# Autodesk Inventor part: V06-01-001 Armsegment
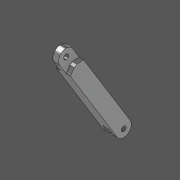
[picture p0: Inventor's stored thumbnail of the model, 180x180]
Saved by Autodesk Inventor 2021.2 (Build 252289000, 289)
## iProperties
RuleStatus: InUse
Company: R-Kon - Rodermund Konstruktion und Entwicklung GmbH
Created: 2020-09
Part Number: V06-01-001 Armsegment
Material: Stahl
Document SubType Name: Modeling
Designer: Felix Rodermund
Engineer: Felix Rodermund
Density: 7.85 g/cm^3
Appearance: Stahl
Mass: 23483.7 g
Surface Area: 1959.26 cm^2
Volume: 2991.55 cm^3
StatusCheck: 1
Title: Teil
Author: Felix Rodermund
Revision Number: 0
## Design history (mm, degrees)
derived "V04-01-000 Gelenkarm Skelett.ipt"
  sketch "yz Armgeometrie"
    geometry: L1 (0, 70.229)-(455.878, 350.229) reference; L2 (455.878, 350.229)-(0, 630.229) reference; L3 (0, -240.046)-(0, 1440.275) reference; L4 (0, 1200.229)-(0, 700.229) reference; L5 (-100, 0.229)-(100, 0.229) reference; L6 (0, 70.229)-(72.973, 600.229) reference; L7 (72.973, 600.229)-(0, 1130.229) reference; L8 (434.944, 384.314)-(-20.935, 104.314) reference; L9 (476.813, 316.145)-(20.935, 36.145) reference; L10 (40, 700.229)-(-40, 700.229) reference; L11 (0, 630.229)-(0, 700.229) reference; L12 (40, 680.229)-(-40, 680.229) reference; L13 (0, 1130.229)-(0, 1200.229) reference; L14 (40, 1200.229)-(-40, 1200.229) reference; A1 r 40 centre (455.878, 350.229) between (476.813, 316.145) and (434.944, 384.314) reference; A2 r 40 centre (0, 70.229) between (20.935, 36.145) and (-20.935, 104.314) reference; 3 further points
    constraints: 1 vertical alignment
  sketch "xz Befestigungslager"
    geometry: L1 (-100, 0)-(100, 0) reference; L2 (100, 0)-(100, 20) reference; L3 (100, 20)-(-100, 20) reference; L4 (-100, 20)-(-100, 0) reference; L5 (140, 0)-(-140, 0) reference; L6 (-15, 20)-(-15, 110.229) reference; L7 (-15, 110.229)-(15, 110.229) reference; L8 (15, 110.229)-(15, 20) reference; L9 (0, 110.229)-(0, 30.229) reference; L10 (-37, 310.229)-(-37, 30.229) reference; L11 (-37, 30.229)-(-17, 30.229) reference; L12 (-17, 30.229)-(-17, 113.229) reference; L13 (-17, 113.229)-(17, 113.229) reference; L14 (17, 113.229)-(17, 30.229) reference; L15 (17, 30.229)-(37, 30.229) reference; L16 (37, 30.229)-(37, 310.229) reference; L17 (0, 390.229)-(0, 310.229) reference; 6 further points
    constraints: 1 other
  sketch "wx Armgelenk"
    geometry: L1 (20.935, 15)-(20.935, -15) reference; L2 (20.935, -15)-(-26.288, -15) reference; L3 (-26.288, 15)-(20.935, 15) reference; L4 (-20.935, -17)-(-20.935, -37) reference; L5 (22.505, -17)-(-20.935, -17) reference; L6 (-20.935, -37)-(125.607, -37) reference; L7 (485, 37)-(485, 15) reference; L8 (485, 15)-(575, 15) reference; L9 (575, 15)-(575, -15) reference; L10 (575, -15)-(485, -15) reference; L11 (485, -15)-(485, -37) reference; L12 (-353.223, 0)-(1265.573, 0) reference; L13 (575, 0)-(495, 0) reference; 2 further points
  sketch "xz Gelenkdetails"
    geometry: L1 (-37, 310.229)-(-37, 30.229) reference; L2 (-37, 30.229)-(-17, 30.229) reference; L3 (-17, 30.229)-(-17, 113.229) reference; L4 (-15, 20)-(-15, 110.229) reference; L5 (-15, 110.229)-(15, 110.229) reference; L6 (15, 110.229)-(15, 20) reference; L7 (37, 30.229)-(37, 310.229) reference; L8 (47, 82.729)-(-47, 82.729) reference; L9 (-47, 82.729)-(-47, 57.729) reference; L10 (-47, 57.729)-(47, 57.729) reference; L11 (47, 57.729)-(47, 82.729) reference; L12 (-15, 57.229)-(15, 57.229) reference; L13 (47, 70.229)-(-47, 70.229) reference; 2 further points
  sketch "yz Kollision"
    geometry: L1 (434.944, 384.314)-(-20.935, 104.314) reference; L2 (476.813, 316.145)-(20.935, 36.145) reference; L3 (20.935, 664.314)-(476.813, 384.314) reference; L4 (-20.935, 596.145)-(434.944, 316.145) reference; L5 (434.944, 316.145)-(476.813, 384.314) reference; L6 (392.338, 358.145)-(434.207, 289.977) reference; L7 (378.42, 349.597)-(416.709, 326.171) reference; L8 (-300.984, -114.635)-(1078.406, 732.585) reference; A1 r 40 centre (455.878, 350.229) between (434.944, 384.314) and (476.813, 316.145) reference; 6 further points; 1 other entity
    constraints: 1 other
  sketch "yz Armsegment Details"
    geometry: C1 r 40 at (455.878, 350.229) reference; C2 r 13 at (455.878, 350.229) reference; 4 further points
    constraints: 1 vertical alignment
sketch "yz basis"
  geometry: L1 (476.813, 316.145)-(20.935, 36.145) reference; L2 (434.944, 384.314)-(-20.935, 104.314) reference; L3 (0, 70.229)-(455.878, 350.229) reference; L4 (378.42, 349.597)-(416.709, 326.171) reference; C1 r 13 at (455.878, 350.229) reference; A1 r 40 centre (455.878, 350.229) between (476.813, 316.145) and (434.944, 384.314) reference; A2 r 40 centre (0, 70.229) between (20.935, 36.145) and (-20.935, 104.314) reference; 1 further point
sketch "xz basis"
  geometry: L1 (37, 30.229)-(37, 310.229) reference; L2 (17, 30.229)-(37, 30.229) reference; L3 (-37, 30.229)-(-17, 30.229) reference; L4 (-37, 310.229)-(-37, 30.229) reference; L5 (-17, 30.229)-(-17, 113.229) reference; L6 (-17, 113.229)-(17, 113.229) reference; L7 (17, 113.229)-(17, 30.229) reference; L8 (-47, 57.729)-(47, 57.729) reference; L9 (47, 57.729)-(47, 82.729) reference; L10 (47, 82.729)-(-47, 82.729) reference; L11 (47, 70.229)-(-47, 70.229) reference; L12 (-47, 82.729)-(-47, 57.729) reference; 1 further point
node "ewx mitte armsegment"
sketch "wx mitte armsegment"
  geometry: L1 (485, -15)-(485, -37) reference; L2 (575, -15)-(485, -15) reference; L3 (485, 37)-(485, 15) reference; L4 (485, 15)-(575, 15) reference; L5 (575, 15)-(575, -15) reference; 1 further point
workplane "Arbeitsebene2"
extrude "Extrusion1" new body sketch "yz basis" stored distance "d3" = 10; taper "d4" = 0 deg
workplane "Arbeitsebene3"
sketch "Skizze8"
  geometry: L1 (-476.813, 285.916)-(-20.935, 5.916) reference; L2 (-434.944, 354.084)-(20.935, 74.084) reference; L3 (-15.706, 96.589)-(-57.575, 28.42); L4 (-57.575, 28.42)-(15.706, -16.589); L5 (15.706, -16.589)-(57.575, 51.58); L6 (57.575, 51.58)-(-15.706, 96.589); A1 r 40 centre (0, 40) between (-20.935, 5.916) and (20.935, 74.084) reference; 5 further points
  constraints: 8 end point, 3 perpendicular, 2 point on line, 1 coincident, 1 collinear, 1 vertical alignment, 4 other
extrude "Extrusion2" cut sketch "Skizze8" stored distance "d5" = 10; taper "d6" = 0 deg
sketch "Skizze9"
  geometry: L1 (485, -15)-(485, -37) reference; L2 (485, 37)-(485, 15) reference; L3 (485, 15)-(575, 15) reference; L4 (575, -15)-(485, -15) reference; L5 (575, -15)-(485, -15); L6 (485, -15)-(485, -105); L7 (485, -105)-(575, -105); L8 (575, -105)-(575, -15); L9 (575, 105)-(485, 105); L10 (485, 105)-(485, 15); L11 (485, 15)-(575, 15); L12 (575, 15)-(575, 105); 1 further point
  constraints: 16 end point, 4 parallel, 3 equal length, 2 horizontal, 2 perpendicular, 1 point on line
extrude "Extrusion3" cut sketch "Skizze9" extent not by distance; stored distance "d7" = 0; taper "d8" = 0 deg
sketch "Skizze11"
  geometry: L1 (-47, 57.729)-(47, 57.729) reference; L2 (47, 70.229)-(-47, 70.229) reference; L3 (47, 57.729)-(47, 70.229); L4 (-47, 57.729)-(-47, 70.229); 1 further point
  constraints: 4 end point, 1 parallel, 1 vertical
revolve "Umdrehung2" sketch "Skizze11" stored, may be unused: angle "d9" = 90 deg
sketch "Skizze13"
  geometry: L1 (378.42, 349.597)-(416.709, 326.171) reference; L2 (416.709, 326.171)-(440.134, 364.46); L3 (440.134, 364.46)-(401.845, 387.886); L4 (401.845, 387.886)-(378.42, 349.597); L5 (0, 70.229)-(455.878, 350.229) reference; L6 (420.289, 281.428)-(416.709, 326.171); L7 (416.709, 326.171)-(461.452, 329.751); L8 (461.452, 329.751)-(465.032, 285.008); L9 (465.032, 285.008)-(420.289, 281.428); 1 further point
  constraints: 14 end point, 4 perpendicular, 4 symmetric about line
extrude "Extrusion4" cut sketch "Skizze13" stored distance "d10" = 10; taper "d11" = 0 deg
extrude "Extrusion5" cut sketch "Skizze13" stored distance "d12" = 10; taper "d13" = 0 deg
extrude "Extrusion6" cut sketch "yz basis" stored distance "d14" = 10; taper "d15" = 0 deg
node "Volumenkörper2"
other parameters: "d2" = 90 deg
